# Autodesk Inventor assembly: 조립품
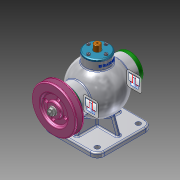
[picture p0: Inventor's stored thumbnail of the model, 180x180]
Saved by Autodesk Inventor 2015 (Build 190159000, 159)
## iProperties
Created: 2025-08
Part Number: 조립품
Document SubType Name: Assembly
Designer: USER
Author: USER
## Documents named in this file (15)
- C:\Users\USER\Downloads\750808V1013\조립품.iam
- C:\Users\USER\Downloads\750808V1013\본체.ipt
- C:\Users\USER\Downloads\750808V1013\가져온 구성요소\V-벨트풀리\V-벨트풀리.ipt
- C:\Users\USER\Downloads\750808V1013\가져온 구성요소\너트 M8\너트 M8.ipt
- C:\Users\USER\Downloads\750808V1013\가져온 구성요소\뒤커버\뒤커버.ipt
- C:\Users\USER\Downloads\750808V1013\가져온 구성요소\베어링- 6202\베어링- 6202.ipt
- C:\Users\USER\Downloads\750808V1013\가져온 구성요소\볼트 M4 x 12\볼트 M4 x 12.ipt
- C:\Users\USER\Downloads\750808V1013\가져온 구성요소\볼트 M4 x 16\볼트 M4 x 16.ipt
- C:\Users\USER\Downloads\750808V1013\가져온 구성요소\상부커버\상부커버.ipt
- C:\Users\USER\Downloads\750808V1013\가져온 구성요소\슬라이드\슬라이드.ipt
- C:\Users\USER\Downloads\750808V1013\가져온 구성요소\앞커버\앞커버.ipt
- C:\Users\USER\Downloads\750808V1013\가져온 구성요소\오일실 15 30 7\오일실 15 30 7.ipt
- C:\Users\USER\Downloads\750808V1013\가져온 구성요소\칼라\칼라.ipt
- C:\Users\USER\Downloads\750808V1013\가져온 구성요소\키 4 x 4 x 12\키 4 x 4 x 12.ipt
- C:\Users\USER\Downloads\750808V1013\가져온 구성요소\편심축\편심축.ipt
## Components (1 placed, 1 different names)
1. V-벨트풀리:1
